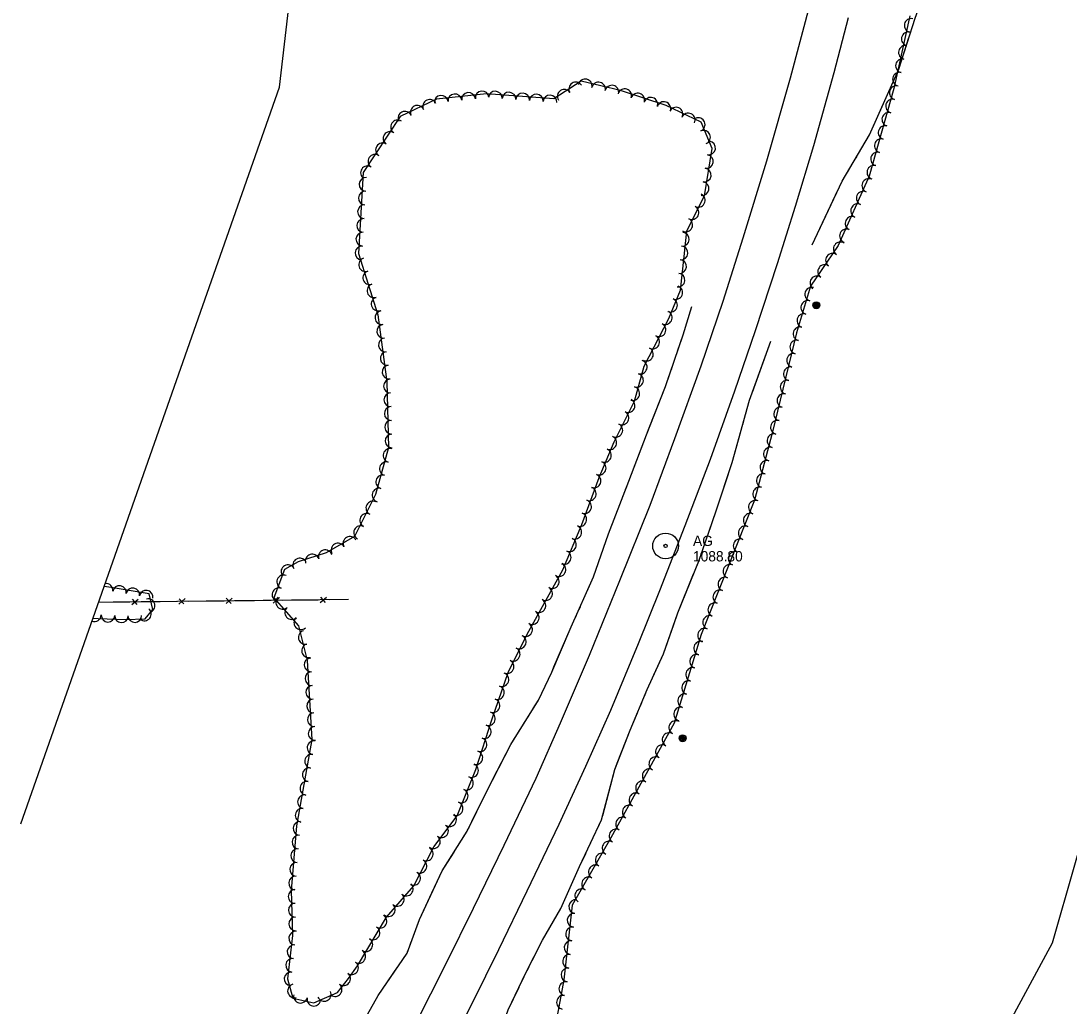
# Model space of a CAD drawing. Extents: x 296807 to 298965, y 28597 to 31038.
# Drawn here: x 297186 to 297798, y 29831 to 30405 of the extents above; entities that cross this region are included whole.
import ezdxf

# ---------------------------------------------------------------- set-up
doc = ezdxf.new("R2010")
doc.units = 0
for name, color, linetype in [('Level 11', 7, 'Continuous'), ('Level 14', 7, 'Continuous'), ('Level 15', 7, 'Continuous'), ('Level 18', 7, 'Continuous'), ('Level 19', 7, 'Continuous'), ('Level 4', 7, 'Continuous'), ('Level 6', 7, 'Continuous')]:
    doc.layers.add(name, color=color, linetype=linetype)

msp = doc.modelspace()

# ---------------------------------------------------------------- linework, layer by layer
at = {"layer": 'Level 11'}
for points in [[(297362.71, 29719.4), (297378.87, 29748.03), (297396.96, 29782.48), (297416.26, 29819.6), (297434.51, 29855.75), (297450.27, 29887.63), (297468.09, 29924.35), (297486.75, 29963.38), (297501.02, 29995.76), (297517.81, 30035.11), (297535.6, 30078.66), (297553.22, 30122.68), (297567.66, 30161.55), (297583.08, 30203.9), (297595.9, 30241.58), (297607.58, 30278.48), (297621.4, 30323.33), (297635.16, 30371.8), (297647.12, 30416.96)], [(297378.59, 29700.24), (297393.58, 29726.65), (297407.83, 29751.86), (297422.11, 29779.13), (297434.82, 29803.7), (297449.75, 29832.81), (297465.06, 29863.61), (297481.42, 29897.68), (297500.11, 29936.74), (297515.73, 29970.53), (297530.3, 30003.09), (297546.5, 30041.89), (297558.97, 30072.8), (297573.69, 30110.86), (297588.38, 30149.4), (297602.59, 30189.2), (297614.71, 30224.55), (297627.47, 30263.56), (297638.09, 30296.89), (297648.67, 30332.34), (297660.56, 30374.97), (297669.04, 30406.87)]]:
    msp.add_lwpolyline(points, dxfattribs=at)
at = {"layer": 'Level 14'}
for centre, radius in [((297650.18, 30239.16), 2.02), ((297650.17, 30239.16), 1.52), ((297650.21, 30239.16), 1.01), ((297650.2, 30239.16), 0.502), ((297572.17, 29986.71), 2.02), ((297572.16, 29986.72), 1.52), ((297572.2, 29986.71), 1.01), ((297572.19, 29986.71), 0.502)]:
    msp.add_circle(centre, radius, dxfattribs=at)
at = {"layer": 'Level 15'}
for p, q in [((297278.39, 30064.92), (297282.02, 30068.15)), ((297278.52, 30068.11), (297281.31, 30065.02)), ((297305.86, 30065.22), (297309.49, 30068.46)), ((297305.99, 30068.42), (297308.78, 30065.32)), ((297333.33, 30065.53), (297336.96, 30068.76)), ((297333.46, 30068.72), (297336.25, 30065.63)), ((297360.8, 30065.83), (297364.42, 30069.07)), ((297360.93, 30069.03), (297363.72, 30065.93)), ((297250.91, 30064.65), (297254.55, 30067.88)), ((297251.05, 30067.84), (297253.84, 30064.74))]:
    msp.add_line(p, q, dxfattribs=at)
for points in [[(297231.59, 30066.17), (297277.51, 30066.62), (297377.29, 30067.73)], [(297231.59, 30066.17), (297239.94, 30066.26)], [(297239.94, 30066.26), (297249.75, 30066.35)], [(297256.24, 30066.41), (297267.41, 30066.52)], [(297267.41, 30066.52), (297277.22, 30066.62)], [(297283.71, 30066.69), (297294.88, 30066.81)], [(297294.88, 30066.81), (297304.69, 30066.92)], [(297311.18, 30066.99), (297322.35, 30067.12)], [(297322.35, 30067.12), (297332.16, 30067.23)], [(297338.65, 30067.3), (297349.82, 30067.42)], [(297349.82, 30067.42), (297359.63, 30067.53)], [(297366.12, 30067.61), (297377.29, 30067.73)]]:
    msp.add_lwpolyline(points, dxfattribs=at)
at = {"layer": 'Level 18'}
for points in [[(297704.63, 30407.83), (297695.4, 30365.61), (297680.92, 30314.43), (297663.01, 30274.03), (297646.69, 30250.38), (297638.63, 30223.04), (297624.5, 30164.51), (297614.04, 30125.53), (297582.95, 30047.26), (297567.19, 29995.48), (297530.36, 29928.72), (297507.78, 29889.47), (297502.86, 29845.93), (297499.09, 29824.81)], [(297399.49, 29882.42), (297415.39, 29900.76), (297427.12, 29923.36), (297440.59, 29941.56), (297451.6, 29968.6), (297461.03, 29997.98), (297470.46, 30025.14), (297481.48, 30047.47), (297502.33, 30084.9), (297513.39, 30111.39), (297523.5, 30138.8), (297532.18, 30159.58), (297544.02, 30183.29), (297549.79, 30203.65), (297564.21, 30231.53), (297570.96, 30247.92), (297573.12, 30267.54), (297574.6, 30282.58), (297584.99, 30302.94), (297589.41, 30330.65), (297582.94, 30345.94), (297562.54, 30355.64), (297536.02, 30364.35), (297512.91, 30369.77), (297497.06, 30359.6), (297457.77, 30362.39), (297428.64, 30359.33), (297407.43, 30349.23), (297385.88, 30316.5), (297383.03, 30269.26), (297394.39, 30233.63), (297399.57, 30194.5), (297400.66, 30156.34), (297393.03, 30128.81), (297380.84, 30104.27), (297364.17, 30094.88), (297347.95, 30089.62), (297339.88, 30085.05), (297333.79, 30068.63), (297348.19, 30052.33), (297353.2, 30032.12), (297355.93, 29986.05), (297347, 29935.64), (297343.92, 29898.03), (297344.52, 29871.69), (297341.72, 29846.56), (297344.73, 29835.2), (297356.96, 29832.5), (297370.78, 29838.47), (297377.19, 29846.7), (297382.45, 29854.12), (297399.49, 29882.42)], [(297228.26, 30056.69), (297231.17, 30056.62), (297247.16, 30055.92), (297258.63, 30056.4), (297263.08, 30061.79), (297260.92, 30070.88), (297238.74, 30074.64), (297234.76, 30075.21)]]:
    msp.add_lwpolyline(points, dxfattribs=at)
for centre, radius, start, end in [((297705.57, 30402.32), 4.01, 77.67699, 257.66167), ((297703.86, 30394.48), 4.01, 77.67699, 257.66167), ((297702.15, 30386.64), 4.01, 77.67699, 257.66167), ((297700.43, 30378.81), 4.01, 77.67699, 257.66167), ((297698.72, 30370.97), 4.01, 77.67699, 257.66167), ((297509.83, 30365.31), 4, 32.70469, 212.68937), ((297515.34, 30367.05), 4, 346.80045, 166.78513), ((297523.13, 30365.23), 4, 346.80045, 166.78513), ((297431.39, 30357.51), 4, 5.99793, 185.98261), ((297439.34, 30358.35), 4, 5.99793, 185.98261), ((297447.29, 30359.18), 4, 5.99793, 185.98261), ((297455.25, 30360.02), 4, 5.99793, 185.98261), ((297462.85, 30359.93), 4, 355.94878, 175.93346), ((297470.82, 30359.36), 4, 355.94878, 175.93346), ((297478.8, 30358.8), 4, 355.94878, 175.93346), ((297486.78, 30358.23), 4, 355.94878, 175.93346), ((297494.75, 30357.66), 4, 355.94878, 175.93346), ((297503.1, 30360.99), 4, 32.70469, 212.68937), ((297530.91, 30363.4), 4, 346.80045, 166.78513), ((297538.45, 30361.35), 4, 341.81549, 161.80017), ((297546.05, 30358.85), 4, 341.81549, 161.80017), ((297696.85, 30363.03), 4.01, 74.20787, 254.19254), ((297417.39, 30351.66), 4, 25.46891, 205.45359), ((297424.61, 30355.09), 4, 25.46891, 205.45359), ((297553.64, 30356.36), 4, 341.81549, 161.80017), ((297561.24, 30353.86), 4, 341.81549, 161.80017), ((297694.67, 30355.31), 4.01, 74.20787, 254.19254), ((297410.17, 30348.22), 4, 25.46891, 205.45359), ((297568.25, 30350.6), 4, 334.58041, 154.56509), ((297575.47, 30347.17), 4, 334.58041, 154.56509), ((297692.48, 30347.59), 4.01, 74.20787, 254.19254), ((297405.9, 30343.11), 4, 56.64892, 236.6336), ((297581.29, 30344.46), 4, 292.95016, 112.93483), ((297690.3, 30339.87), 4.01, 74.20787, 254.19254), ((297401.51, 30336.43), 4, 56.64892, 236.6336), ((297584.41, 30337.09), 4, 292.95016, 112.93483), ((297397.11, 30329.75), 4, 56.64892, 236.6336), ((297587.32, 30330.87), 4, 260.93779, 80.92247), ((297688.11, 30332.15), 4.01, 74.20787, 254.19254), ((297392.71, 30323.07), 4, 56.64892, 236.6336), ((297586.06, 30322.97), 4, 260.93779, 80.92247), ((297685.93, 30324.43), 4.01, 74.20787, 254.19254), ((297388.32, 30316.39), 4, 56.64892, 236.6336), ((297584.8, 30315.07), 4, 260.93779, 80.92247), ((297683.74, 30316.71), 4.01, 74.20787, 254.19254), ((297387.56, 30309.64), 4, 86.55313, 266.53781), ((297680.79, 30308.95), 4.01, 66.10573, 246.09041), ((297583.54, 30307.18), 4, 260.93779, 80.92247), ((297387.08, 30301.65), 4, 86.55313, 266.53781), ((297581.28, 30300.29), 4, 242.98072, 62.9654), ((297677.53, 30301.61), 4.01, 66.10573, 246.09041), ((297386.6, 30293.67), 4, 86.55313, 266.53781), ((297577.65, 30293.17), 4, 242.98072, 62.9654), ((297674.28, 30294.28), 4.01, 66.10573, 246.09041), ((297386.12, 30285.69), 4, 86.55313, 266.53781), ((297574.02, 30286.05), 4, 242.98072, 62.9654), ((297671.03, 30286.94), 4.01, 66.10573, 246.09041), ((297667.78, 30279.6), 4.01, 66.10573, 246.09041), ((297385.64, 30277.71), 4, 86.55313, 266.53781), ((297572.01, 30277.64), 4, 264.39212, 84.3768), ((297664.18, 30272.02), 4.01, 55.39862, 235.3833), ((297385.16, 30269.72), 4, 86.55313, 266.53781), ((297571.23, 30269.68), 4, 264.39212, 84.3768), ((297387.27, 30262.84), 4, 107.69144, 287.67612), ((297570.38, 30261.75), 4, 263.71715, 83.70183), ((297659.62, 30265.41), 4.01, 55.39862, 235.3833), ((297389.7, 30255.22), 4, 107.69144, 287.67612), ((297569.5, 30253.8), 4, 263.71715, 83.70183), ((297655.06, 30258.81), 4.01, 55.39862, 235.3833), ((297392.13, 30247.6), 4, 107.69144, 287.67612), ((297650.5, 30252.2), 4.01, 55.39862, 235.3833), ((297568.14, 30246.58), 4, 247.60959, 67.59427), ((297647.47, 30245.6), 4.01, 73.57762, 253.5623), ((297394.56, 30239.98), 4, 107.69144, 287.67612), ((297565.1, 30239.19), 4, 247.60959, 67.59427), ((297645.2, 30237.91), 4.01, 73.57762, 253.5623), ((297396.72, 30231.93), 4, 97.55291, 277.53758), ((297562.08, 30231.98), 4, 242.67763, 62.66231), ((297642.93, 30230.21), 4.01, 73.57762, 253.5623), ((297397.77, 30224), 4, 97.55291, 277.53758), ((297558.41, 30224.88), 4, 242.67763, 62.66231), ((297554.74, 30217.77), 4, 242.67763, 62.66231), ((297640.66, 30222.51), 4.01, 73.57762, 253.5623), ((297398.82, 30216.07), 4, 97.55291, 277.53758), ((297638.8, 30214.82), 4.01, 76.43554, 256.42021), ((297399.87, 30208.14), 4, 97.55291, 277.53758), ((297551.07, 30210.67), 4, 242.67763, 62.66231), ((297636.92, 30207.02), 4.01, 76.43554, 256.42021), ((297400.92, 30200.22), 4, 97.55291, 277.53758), ((297547.46, 30203.09), 4, 254.18052, 74.1652), ((297635.04, 30199.21), 4.01, 76.43554, 256.42021), ((297545.28, 30195.39), 4, 254.18052, 74.1652), ((297401.73, 30192.05), 4, 91.64814, 271.63282), ((297543.1, 30187.7), 4, 254.18052, 74.1652), ((297633.15, 30191.41), 4.01, 76.43554, 256.42021), ((297401.96, 30184.06), 4, 91.64814, 271.63282), ((297540.36, 30180.64), 4, 243.47064, 63.45532), ((297631.27, 30183.61), 4.01, 76.43554, 256.42021), ((297402.19, 30176.07), 4, 91.64814, 271.63282), ((297629.39, 30175.81), 4.01, 76.43554, 256.42021), ((297402.42, 30168.07), 4, 91.64814, 271.63282), ((297536.79, 30173.49), 4, 243.47064, 63.45532), ((297627.5, 30168.01), 4.01, 76.43554, 256.42021), ((297533.22, 30166.33), 4, 243.47064, 63.45532), ((297402.65, 30160.08), 4, 91.64814, 271.63282), ((297529.68, 30159.01), 4, 247.34259, 67.32727), ((297625.51, 30160.19), 4.01, 74.98141, 254.96609), ((297401.53, 30151.62), 4, 74.50137, 254.48605), ((297526.59, 30151.63), 4, 247.34259, 67.32727), ((297623.43, 30152.44), 4.01, 74.98141, 254.96609), ((297399.39, 30143.92), 4, 74.50137, 254.48605), ((297523.51, 30144.25), 4, 247.34259, 67.32727), ((297621.35, 30144.69), 4.01, 74.98141, 254.96609), ((297397.25, 30136.21), 4, 74.50137, 254.48605), ((297520.51, 30136.74), 4, 249.74618, 69.73086), ((297619.27, 30136.94), 4.01, 74.98141, 254.96609), ((297395.11, 30128.51), 4, 74.50137, 254.48605), ((297517.75, 30129.24), 4, 249.74618, 69.73086), ((297617.19, 30129.19), 4.01, 74.98141, 254.96609), ((297391.46, 30120.95), 4, 63.59692, 243.5816), ((297514.98, 30121.74), 4, 249.74618, 69.73086), ((297614.63, 30121.34), 4.01, 68.35065, 248.33533), ((297387.9, 30113.79), 4, 63.59692, 243.5816), ((297512.21, 30114.24), 4, 249.74618, 69.73086), ((297611.67, 30113.88), 4.01, 68.35065, 248.33533), ((297384.35, 30106.63), 4, 63.59692, 243.5816), ((297509.25, 30106.9), 4, 247.35786, 67.34254), ((297608.71, 30106.42), 4.01, 68.35065, 248.33533), ((297371.13, 30096.4), 4, 29.42121, 209.40588), ((297378.1, 30100.32), 4, 29.42121, 209.40588), ((297506.17, 30099.52), 4, 247.35786, 67.34254), ((297605.75, 30098.96), 4.01, 68.35065, 248.33533), ((297356.08, 30090.05), 4, 17.95824, 197.94291), ((297363.69, 30092.52), 4, 17.95824, 197.94291), ((297503.09, 30092.14), 4, 247.35786, 67.34254), ((297602.78, 30091.51), 4.01, 68.35065, 248.33533), ((297341.91, 30083.8), 4, 29.53032, 209.515), ((297348.87, 30087.74), 4, 29.53032, 209.515), ((297500.01, 30085.03), 4, 240.88111, 60.86578), ((297599.82, 30084.05), 4.01, 68.35065, 248.33533), ((297339.46, 30077.91), 4, 69.65839, 249.64307), ((297496.12, 30078.04), 4, 240.88111, 60.86578), ((297596.86, 30076.59), 4.01, 68.35065, 248.33533), ((297235.95, 30072.96), 3.94, 351.92388, 98.98923), ((297243.68, 30071.71), 3.94, 350.36358, 170.34826), ((297251.45, 30070.39), 3.94, 350.36358, 170.34826), ((297336.68, 30070.41), 4, 69.65839, 249.64307), ((297492.22, 30071.06), 4, 240.88111, 60.86578), ((297259.23, 30069.07), 3.94, 350.36358, 170.34826), ((297260.42, 30064.05), 3.94, 283.37885, 103.36353), ((297338.88, 30066.03), 4, 131.48023, 311.46491), ((297593.9, 30069.13), 4.01, 68.35065, 248.33533), ((297258.26, 30059.2), 3.94, 230.42792, 50.4126), ((297344.17, 30060.04), 4, 131.48023, 311.46491), ((297488.33, 30064.07), 4, 240.88111, 60.86578), ((297590.94, 30061.67), 4.01, 68.35065, 248.33533), ((297229.08, 30058.73), 3.94, 249.13144, 358.59439), ((297237, 30058.43), 3.94, 177.5021, 357.48678), ((297244.88, 30058.08), 3.94, 177.5021, 357.48678), ((297252.58, 30058.21), 3.94, 182.45492, 2.4396), ((297349.47, 30054.04), 4, 131.48023, 311.46491), ((297484.44, 30057.09), 4, 240.88111, 60.86578), ((297587.98, 30054.22), 4.01, 68.35065, 248.33533), ((297480.55, 30050.1), 4, 240.88111, 60.86578), ((297585.02, 30046.76), 4.01, 68.35065, 248.33533), ((297352.04, 30045.5), 4, 103.92974, 283.91442), ((297476.88, 30042.88), 4, 243.74619, 63.73087), ((297353.97, 30037.74), 4, 103.92974, 283.91442), ((297473.34, 30035.71), 4, 243.74619, 63.73087), ((297582.71, 30039.25), 4.01, 73.07561, 253.06029), ((297355.45, 30029.52), 4, 93.39862, 273.38329), ((297469.8, 30028.54), 4, 243.74619, 63.73087), ((297580.38, 30031.58), 4.01, 73.07561, 253.06029), ((297355.92, 30021.54), 4, 93.39862, 273.38329), ((297578.04, 30023.9), 4.01, 73.07561, 253.06029), ((297466.76, 30020.87), 4, 250.86491, 70.84959), ((297575.7, 30016.22), 4.01, 73.07561, 253.06029), ((297356.4, 30013.55), 4, 93.39862, 273.38329), ((297464.14, 30013.32), 4, 250.86491, 70.84959), ((297356.87, 30005.57), 4, 93.39862, 273.38329), ((297461.52, 30005.76), 4, 250.86491, 70.84959), ((297573.36, 30008.55), 4.01, 73.07561, 253.06029), ((297357.34, 29997.59), 4, 93.39862, 273.38329), ((297458.89, 29998.16), 4, 252.21036, 72.19504), ((297571.03, 30000.87), 4.01, 73.07561, 253.06029), ((297568.18, 29992.93), 4.01, 61.12065, 241.10533), ((297357.82, 29989.61), 4, 93.39862, 273.38329), ((297456.45, 29990.55), 4, 252.21036, 72.19504), ((297564.31, 29985.91), 4.01, 61.12065, 241.10533), ((297357.2, 29981.2), 4, 79.95929, 259.94397), ((297454, 29982.93), 4, 252.21036, 72.19504), ((297560.43, 29978.88), 4.01, 61.12065, 241.10533), ((297355.8, 29973.32), 4, 79.95929, 259.94397), ((297451.56, 29975.32), 4, 252.21036, 72.19504), ((297449.05, 29967.9), 4, 247.85646, 67.84114), ((297556.56, 29971.85), 4.01, 61.12065, 241.10533), ((297354.41, 29965.45), 4, 79.95929, 259.94397), ((297446.04, 29960.49), 4, 247.85646, 67.84114), ((297552.68, 29964.83), 4.01, 61.12065, 241.10533), ((297353.01, 29957.57), 4, 79.95929, 259.94397), ((297548.8, 29957.8), 4.01, 61.12065, 241.10533), ((297351.62, 29949.7), 4, 79.95929, 259.94397), ((297443.02, 29953.08), 4, 247.85646, 67.84114), ((297544.93, 29950.78), 4.01, 61.12065, 241.10533), ((297350.22, 29941.83), 4, 79.95929, 259.94397), ((297440.01, 29945.68), 4, 247.85646, 67.84114), ((297541.05, 29943.75), 4.01, 61.12065, 241.10533), ((297436.29, 29939.26), 4, 233.50065, 53.48532), ((297537.17, 29936.72), 4.01, 61.12065, 241.10533), ((297348.98, 29934.13), 4, 85.3333, 265.31798), ((297431.53, 29932.84), 4, 233.50065, 53.48532), ((297533.3, 29929.7), 4.01, 61.12065, 241.10533), ((297348.32, 29926.16), 4, 85.3333, 265.31798), ((297426.78, 29926.41), 4, 233.50065, 53.48532), ((297347.67, 29918.19), 4, 85.3333, 265.31798), ((297422.61, 29919.22), 4, 242.5639, 62.54858), ((297529.31, 29922.69), 4.01, 60.09785, 240.08253), ((297418.93, 29912.12), 4, 242.5639, 62.54858), ((297525.31, 29915.73), 4.01, 60.09785, 240.08253), ((297347.02, 29910.22), 4, 85.3333, 265.31798), ((297521.31, 29908.78), 4.01, 60.09785, 240.08253), ((297346.37, 29902.25), 4, 85.3333, 265.31798), ((297415.24, 29905.03), 4, 242.5639, 62.54858), ((297517.31, 29901.82), 4.01, 60.09785, 240.08253), ((297346.1, 29894.49), 4, 91.29287, 271.27754), ((297411, 29898.9), 4, 229.10529, 49.08997), ((297513.31, 29894.87), 4.01, 60.09785, 240.08253), ((297405.77, 29892.85), 4, 229.10529, 49.08997), ((297509.8, 29888.65), 4.01, 83.5638, 263.54848), ((297346.28, 29886.49), 4, 91.29287, 271.27754), ((297400.53, 29886.81), 4, 229.10529, 49.08997), ((297508.9, 29880.67), 4.01, 83.5638, 263.54848), ((297346.46, 29878.5), 4, 91.29287, 271.27754), ((297395.64, 29880.07), 4, 238.94246, 58.92714), ((297346.46, 29870.23), 4, 83.66272, 263.64739), ((297391.51, 29873.22), 4, 238.94246, 58.92714), ((297508, 29872.7), 4.01, 83.5638, 263.54848), ((297345.57, 29862.28), 4, 83.66272, 263.64739), ((297387.39, 29866.37), 4, 238.94246, 58.92714), ((297507.1, 29864.73), 4.01, 83.5638, 263.54848), ((297383.26, 29859.52), 4, 238.94246, 58.92714), ((297506.2, 29856.75), 4.01, 83.5638, 263.54848), ((297344.69, 29854.34), 4, 83.66272, 263.64739), ((297379.03, 29852.92), 4, 234.69687, 54.68155), ((297343.81, 29846.39), 4, 83.66272, 263.64739), ((297374.4, 29846.52), 4, 232.11197, 52.09665), ((297505.3, 29848.78), 4.01, 83.5638, 263.54848), ((297345.77, 29839.42), 4, 104.82568, 284.81036), ((297369.49, 29840.21), 4, 232.11197, 52.09665), ((297504.07, 29840.72), 4.01, 79.89276, 259.87744), ((297349.26, 29836.34), 4, 167.57506, 347.55974), ((297363.15, 29837.45), 4, 203.36021, 23.34489), ((297502.66, 29832.82), 4.01, 79.89276, 259.87744), ((297357.07, 29834.62), 4, 167.57506, 347.55974)]:
    msp.add_arc(centre, radius, start, end, dxfattribs=at)
at = {"layer": 'Level 19'}
for points in [[(297647.8, 30274.42), (297665.2, 30311.43), (297681.24, 30338.46), (297698.28, 30376.88), (297707.78, 30406.57), (297716.33, 30430.57), (297721.43, 30447.48), (297713.98, 30446.89)], [(297705.64, 30399.86), (297706.39, 30402.2)], [(297691.66, 30361.96), (297698.28, 30376.88), (297704.14, 30395.19)], [(297676.22, 30330.01), (297681.24, 30338.46), (297691.66, 30361.96)], [(297672.48, 30323.69), (297673.73, 30325.8)], [(297668.73, 30317.38), (297669.98, 30319.48)], [(297665.02, 30311.04), (297665.2, 30311.43), (297666.23, 30313.17)], [(297647.8, 30274.42), (297662.93, 30306.6)], [(297350.88, 29767.35), (297361.11, 29782.29), (297377.72, 29806.62), (297394.58, 29836.84), (297411.42, 29861.38), (297418.63, 29881.04), (297431.92, 29909.51), (297446.53, 29932.57), (297457.72, 29955.4), (297471.91, 29983.11), (297488.14, 30008.97), (297495.82, 30025.29), (297507.25, 30051.69), (297520.23, 30080.88), (297528.99, 30105.94), (297540.87, 30136.71), (297551.03, 30163.61), (297562.22, 30191.77), (297572.48, 30221.96), (297577.55, 30238.36)], [(297569.25, 30212.46), (297572.48, 30221.96), (297577.55, 30238.36)], [(297464.74, 29812.46), (297470.43, 29828.48), (297480.81, 29849.89), (297490.47, 29869.08), (297501.21, 29887.56), (297512.11, 29911.88), (297524.86, 29939.09), (297532.62, 29968.59), (297541.65, 29991.46), (297551.52, 30015.16), (297561.11, 30035.94), (297569.46, 30059.8), (297581.59, 30089.97), (297591.72, 30119.42), (297601.17, 30147.44), (297611.21, 30183.78), (297623.7, 30218.33)], [(297612.92, 30188.54), (297623.7, 30218.33)], [(297567.44, 30207.14), (297568.04, 30208.91)], [(297565.63, 30201.81), (297566.23, 30203.58)], [(297563.82, 30196.48), (297564.42, 30198.26)], [(297552.63, 30167.63), (297562.22, 30191.77), (297562.61, 30192.93)], [(297610.81, 30182.34), (297611.21, 30183.78), (297611.44, 30184.43)], [(297609.06, 30176.02), (297609.64, 30178.13)], [(297542.95, 30142.22), (297551.03, 30163.61), (297552.63, 30167.63)], [(297607.32, 30169.7), (297607.9, 30171.81)], [(297597.03, 30135.16), (297601.17, 30147.44), (297606.15, 30165.49)], [(297540.96, 30136.96), (297541.63, 30138.71)], [(297538.94, 30131.7), (297539.61, 30133.45)], [(297586.82, 30105.17), (297591.72, 30119.42), (297597.03, 30135.16)], [(297536.91, 30126.45), (297537.59, 30128.2)], [(297526.04, 30097.48), (297528.99, 30105.94), (297535.56, 30122.95)], [(297584.69, 30098.97), (297585.4, 30101.04)], [(297516.33, 30072.1), (297520.23, 30080.88), (297526.04, 30097.48)], [(297582.55, 30092.77), (297583.26, 30094.84)], [(297580.25, 30086.64), (297581.06, 30088.67)], [(297567.11, 30053.08), (297569.46, 30059.8), (297578.62, 30082.58)], [(297514.04, 30066.96), (297514.8, 30068.67)], [(297511.76, 30061.82), (297512.52, 30063.53)], [(297509.47, 30056.67), (297510.23, 30058.39)], [(297497.12, 30028.29), (297507.25, 30051.69), (297507.94, 30053.25)], [(297555.45, 30023.67), (297561.11, 30035.94), (297567.11, 30053.08)], [(297485.02, 30003.99), (297488.14, 30008.97), (297495.82, 30025.29), (297497.12, 30028.29)], [(297552.7, 30017.71), (297553.62, 30019.7)], [(297550.08, 30011.71), (297550.92, 30013.72)], [(297547.56, 30005.65), (297548.4, 30007.67)], [(297482.03, 29999.22), (297483.02, 30000.81)], [(297534.05, 29972.23), (297541.65, 29991.46), (297545.88, 30001.62)], [(297479.04, 29994.46), (297480.03, 29996.05)], [(297476.04, 29989.69), (297477.04, 29991.28)], [(297461.35, 29962.48), (297471.91, 29983.11), (297474.05, 29986.51)], [(297525.56, 29941.74), (297532.62, 29968.59), (297534.05, 29972.23)], [(297449.26, 29938.14), (297457.72, 29955.4), (297461.35, 29962.48)], [(297446.78, 29933.09), (297447.61, 29934.78)], [(297523.24, 29935.63), (297524.17, 29937.61)], [(297443.83, 29928.31), (297444.83, 29929.9)], [(297520.46, 29929.7), (297521.39, 29931.67)], [(297440.82, 29923.57), (297441.83, 29925.15)], [(297517.68, 29923.76), (297518.61, 29925.74)], [(297425.88, 29896.56), (297431.92, 29909.51), (297438.82, 29920.4)], [(297502.73, 29890.96), (297512.11, 29911.88), (297515.83, 29919.8)], [(297415.17, 29871.6), (297418.63, 29881.04), (297425.88, 29896.56)], [(297487.51, 29863.2), (297490.47, 29869.08), (297501.21, 29887.56), (297502.73, 29890.96)], [(297413.23, 29866.32), (297413.88, 29868.08)], [(297411.22, 29861.08), (297411.42, 29861.38), (297411.94, 29862.8)], [(297408.03, 29856.44), (297409.1, 29857.99)], [(297484.57, 29857.35), (297485.55, 29859.3)], [(297391.09, 29830.58), (297394.58, 29836.84), (297405.91, 29853.35)], [(297481.62, 29851.5), (297482.6, 29853.45)], [(297478.74, 29845.61), (297479.69, 29847.58)], [(297464.74, 29812.46), (297470.43, 29828.48), (297476.83, 29841.68)]]:
    msp.add_lwpolyline(points, dxfattribs=at)
at = {"layer": 'Level 4'}
for points in [[(297186.21, 29936.92), (297336.94, 30366.3), (297365.1, 30607.27), (297394.48, 30861.31)], [(297569.31, 29463.18), (297788.03, 29867.51), (297944.29, 30413.21), (297962.48, 30592.06)]]:
    msp.add_lwpolyline(points, dxfattribs=at)
at = {"layer": 'Level 6'}
for radius in [7.5, 0.96]:
    msp.add_circle((297562.24, 30098.84), radius, dxfattribs=at)

# ---------------------------------------------------------------- texts
for s, p in [('AG', (297578.24, 30098.84)), ('1088.80', (297578.24, 30089.84))]:
    msp.add_text(s, height=6, dxfattribs=at).set_placement(p)

doc.saveas('drawing.dxf')
